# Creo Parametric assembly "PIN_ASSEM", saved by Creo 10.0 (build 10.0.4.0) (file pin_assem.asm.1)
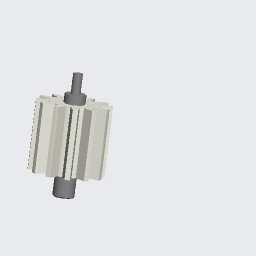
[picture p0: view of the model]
Units: millimeter Kilogram Sec (mmKs); MM, KILOGRAM, SECS

Created from: XX_MMKS_ASM_DESIGN_ABS.ASM

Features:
  1. datum plane "ASM_RIGHT"
  2. datum plane "ASM_TOP"
  3. datum plane "ASM_FRONT"
  4. coordinate system
  5. component "PIN"
  6. component "PIN_GEAR"

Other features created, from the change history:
  component "PIN_GEAR.PRT"
  component "PIN.PRT"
